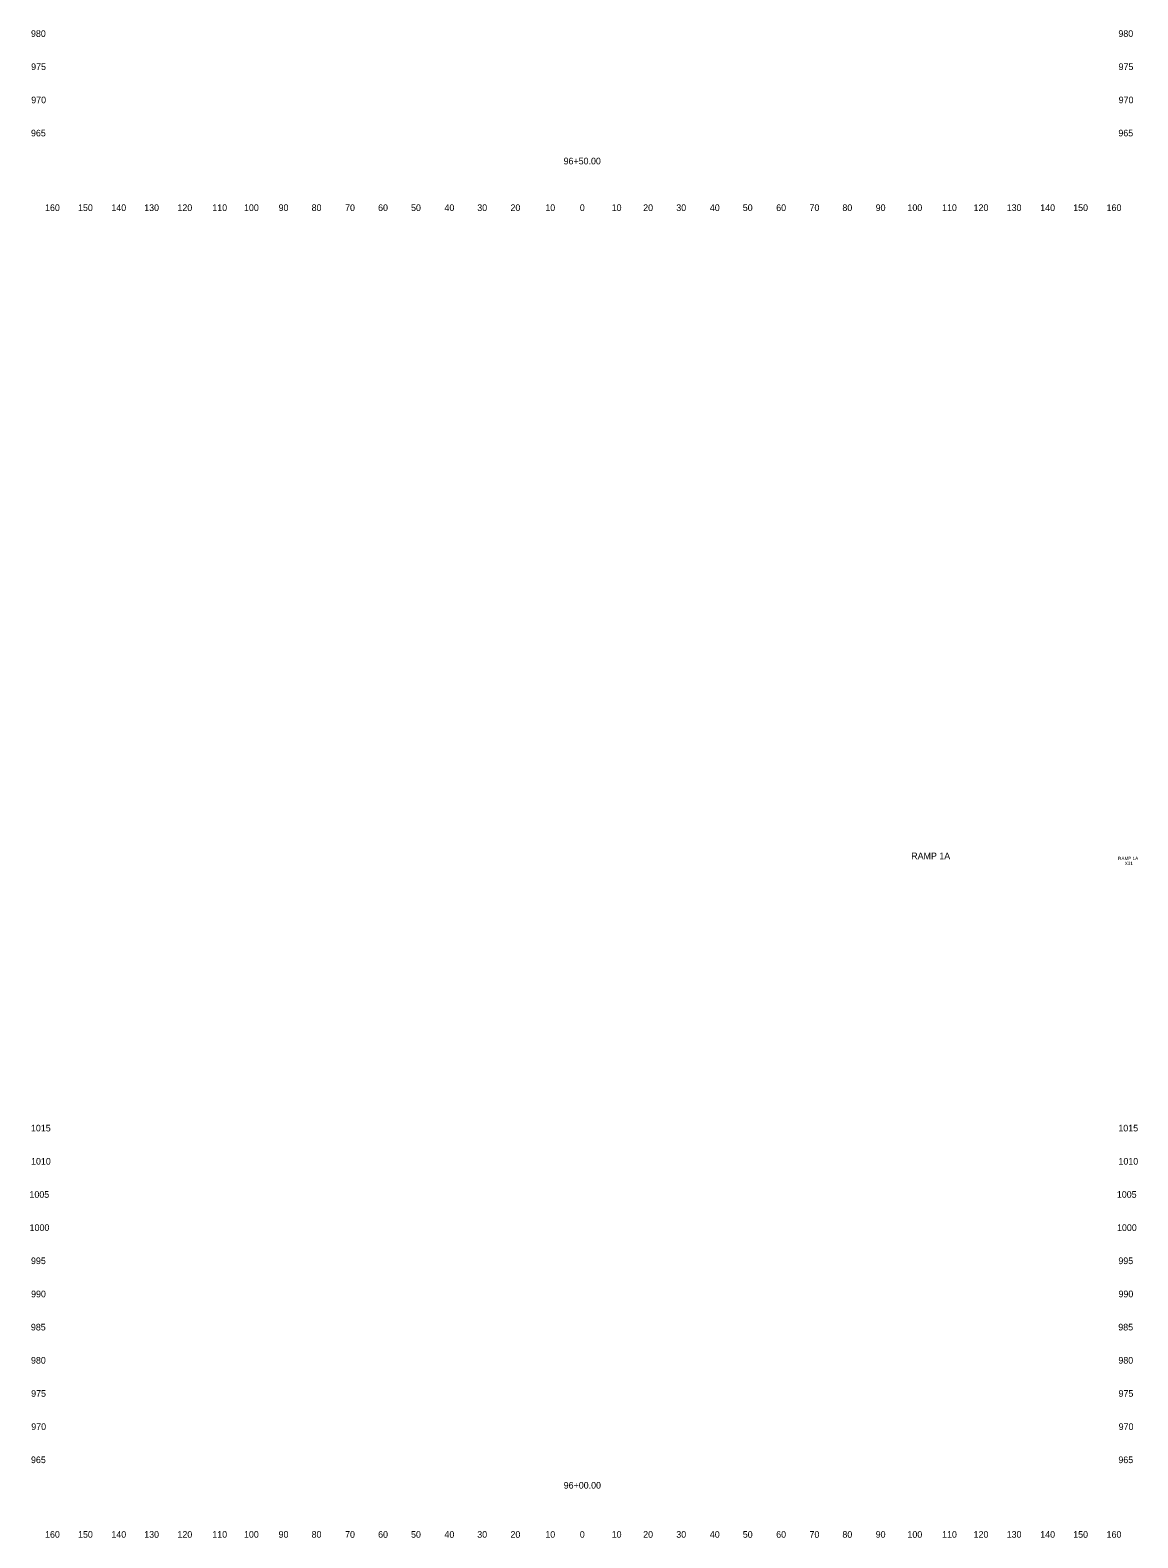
# Model space of a CAD drawing. Extents: x 4994 to 6873, y 4997 to 8804.
# Drawn here: x 6538.6 to 6872.5, y 4997.5 to 5452 of the extents above; entities that cross this region are included whole.
import ezdxf

# ---------------------------------------------------------------- set-up
doc = ezdxf.new("R2010")
doc.units = 0
for name, color, linetype in [('RD_SHT_ID', 7, 'Continuous'), ('RD_XS_TX_Offset', 7, 'Continuous'), ('RD_XS_TX_Station', 7, 'Continuous')]:
    doc.layers.add(name, color=color, linetype=linetype)

msp = doc.modelspace()

# ---------------------------------------------------------------- texts
at = {"layer": 'RD_SHT_ID'}
for s, height, p in [('RAMP 1A', 2, (6804.21, 5202.06)), ('RAMP 1A', 1, (6866.57, 5201.8)), ('X31', 1, (6868.57, 5200.3))]:
    msp.add_text(s, height=height, dxfattribs=at).set_placement(p)
at = {"layer": 'RD_XS_TX_Offset'}
for s, p in [('980', (6538.86, 5450)), ('980', (6866.66, 5450)), ('975', (6538.91, 5440)), ('975', (6866.71, 5440)), ('970', (6538.94, 5430)), ('970', (6866.74, 5430)), ('965', (6538.86, 5420)), ('965', (6866.66, 5420)), ('160', (6543.1, 5397.5)), ('150', (6553.04, 5397.5)), ('140', (6563.1, 5397.5)), ('130', (6572.99, 5397.5)), ('120', (6583.01, 5397.5)), ('110', (6593.51, 5397.5)), ('100', (6603.07, 5397.5)), ('90', (6613.5, 5397.5)), ('80', (6623.46, 5397.5)), ('70', (6633.54, 5397.5)), ('60', (6643.5, 5397.5)), ('50', (6653.43, 5397.5)), ('40', (6663.5, 5397.5)), ('30', (6673.39, 5397.5)), ('20', (6683.4, 5397.5)), ('10', (6693.91, 5397.5)), ('0', (6704.3, 5397.5)), ('0', (6704.3, 5397.5)), ('10', (6713.91, 5397.5)), ('20', (6723.4, 5397.5)), ('30', (6733.39, 5397.5)), ('40', (6743.5, 5397.5)), ('50', (6753.43, 5397.5)), ('60', (6763.5, 5397.5)), ('70', (6773.54, 5397.5)), ('80', (6783.46, 5397.5)), ('90', (6793.5, 5397.5)), ('100', (6803.07, 5397.5)), ('110', (6813.51, 5397.5)), ('120', (6823.01, 5397.5)), ('130', (6832.99, 5397.5)), ('140', (6843.1, 5397.5)), ('150', (6853.04, 5397.5)), ('160', (6863.1, 5397.5)), ('1015', (6538.85, 5120)), ('1015', (6866.65, 5120)), ('1010', (6538.88, 5110)), ('1010', (6866.68, 5110)), ('1005', (6538.4, 5100)), ('1005', (6866.2, 5100)), ('1000', (6538.44, 5090)), ('1000', (6866.24, 5090)), ('995', (6538.86, 5080)), ('995', (6866.66, 5080)), ('990', (6538.89, 5070)), ('990', (6866.69, 5070)), ('985', (6538.83, 5060)), ('985', (6866.63, 5060)), ('980', (6538.86, 5050)), ('980', (6866.66, 5050)), ('975', (6538.91, 5040)), ('975', (6866.71, 5040)), ('970', (6538.94, 5030)), ('970', (6866.74, 5030)), ('965', (6538.86, 5020)), ('965', (6866.66, 5020)), ('160', (6543.1, 4997.5)), ('150', (6553.04, 4997.5)), ('140', (6563.1, 4997.5)), ('130', (6572.99, 4997.5)), ('120', (6583.01, 4997.5)), ('110', (6593.51, 4997.5)), ('100', (6603.07, 4997.5)), ('90', (6613.5, 4997.5)), ('80', (6623.46, 4997.5)), ('70', (6633.54, 4997.5)), ('60', (6643.5, 4997.5)), ('50', (6653.43, 4997.5)), ('40', (6663.5, 4997.5)), ('30', (6673.39, 4997.5)), ('20', (6683.4, 4997.5)), ('10', (6693.91, 4997.5)), ('0', (6704.3, 4997.5)), ('0', (6704.3, 4997.5)), ('10', (6713.91, 4997.5)), ('20', (6723.4, 4997.5)), ('30', (6733.39, 4997.5)), ('40', (6743.5, 4997.5)), ('50', (6753.43, 4997.5)), ('60', (6763.5, 4997.5)), ('70', (6773.54, 4997.5)), ('80', (6783.46, 4997.5)), ('90', (6793.5, 4997.5)), ('100', (6803.07, 4997.5)), ('110', (6813.51, 4997.5)), ('120', (6823.01, 4997.5)), ('130', (6832.99, 4997.5)), ('140', (6843.1, 4997.5)), ('150', (6853.04, 4997.5)), ('160', (6863.1, 4997.5))]:
    msp.add_text(s, height=2, dxfattribs=at).set_placement(p)
at = {"layer": 'RD_XS_TX_Station'}
for s, p in [('96+50.00', (6699.42, 5411.56)), ('96+00.00', (6699.45, 5012.31))]:
    msp.add_text(s, height=2, dxfattribs=at).set_placement(p)

doc.saveas('drawing.dxf')
